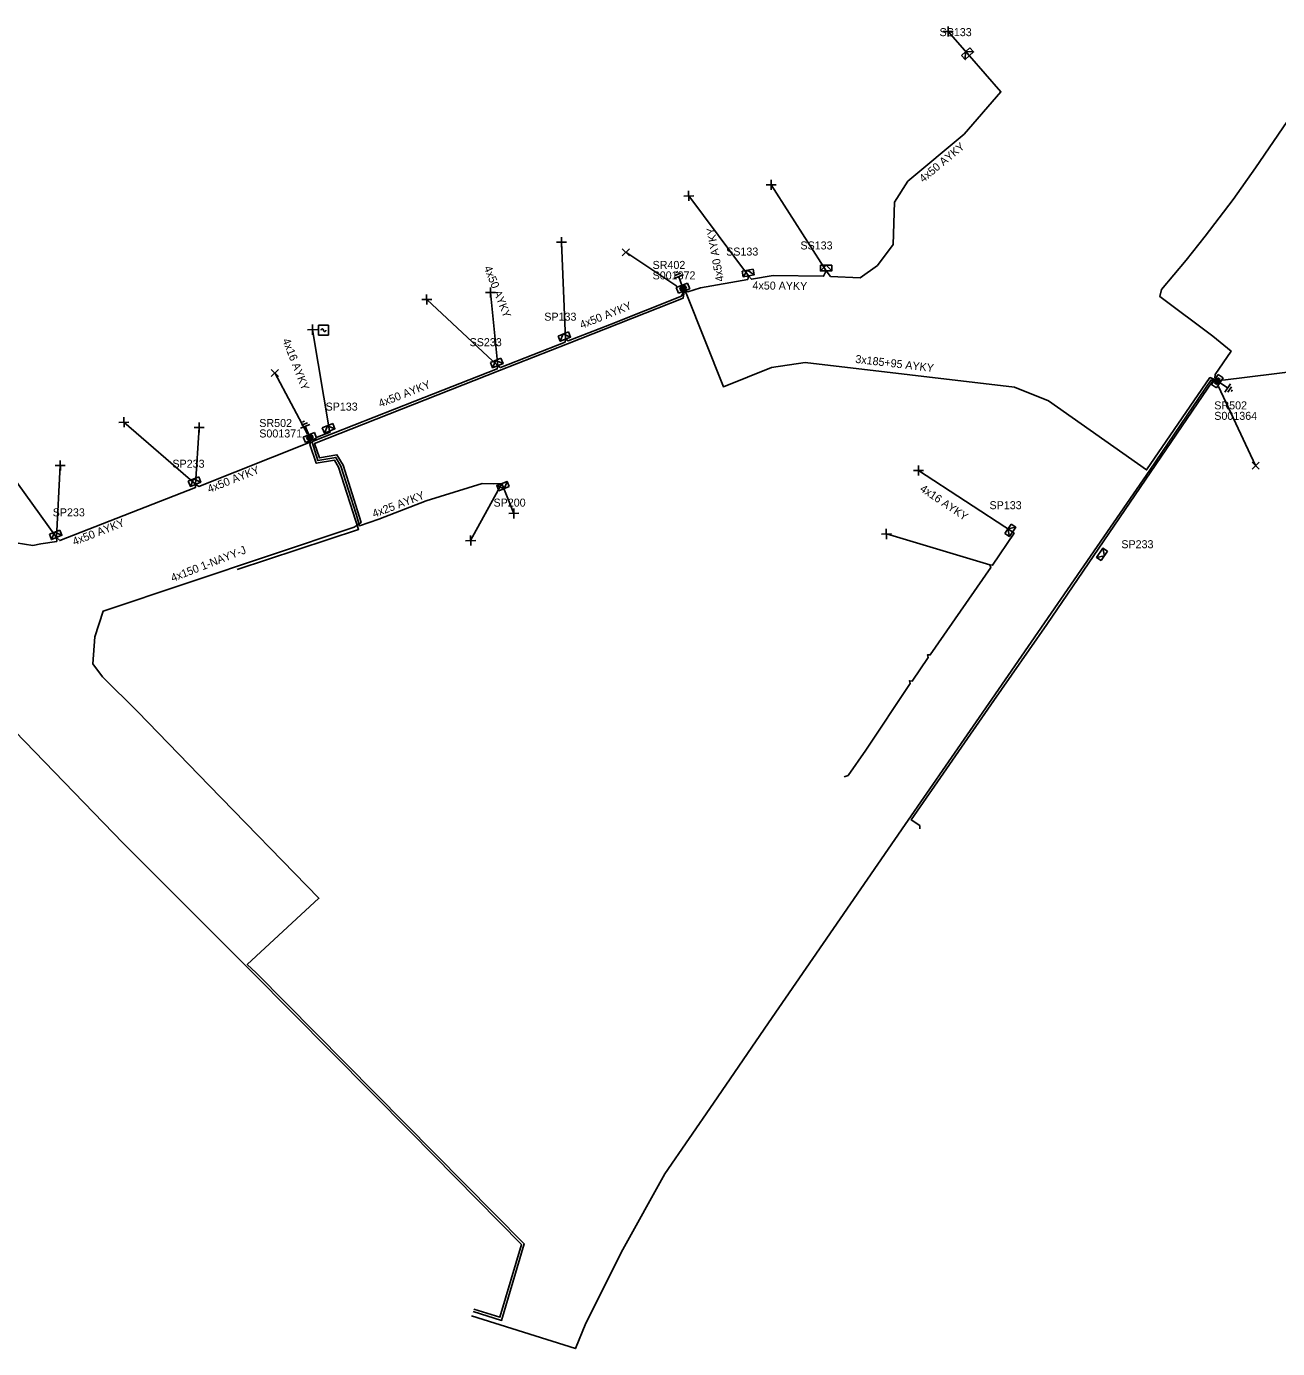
# Model space of a CAD drawing. Extents: x -762284 to -761419, y -1155250 to -1154991.
# Drawn here: x -761732.3 to -761576.8, y -1155250.1 to -1155085.8 of the extents above; entities that cross this region are included whole.
import ezdxf

# ---------------------------------------------------------------- set-up
doc = ezdxf.new("R2010")
doc.units = 0
for name, color, linetype in [('Vrstva 15', 7, 'Continuous'), ('Vrstva 28', 7, 'Continuous'), ('Vrstva 29', 7, 'Continuous'), ('Vrstva 30', 7, 'Continuous'), ('Vrstva 31', 7, 'Continuous'), ('Vrstva 33', 7, 'Continuous'), ('Vrstva 34', 7, 'Continuous'), ('Vrstva 5', 7, 'Continuous'), ('Vrstva 59', 7, 'Continuous'), ('Vrstva 6', 7, 'Continuous')]:
    doc.layers.add(name, color=color, linetype=linetype)

msp = doc.modelspace()

# ---------------------------------------------------------------- linework, layer by layer
at = {"layer": 'Vrstva 15'}
for points in [[(-761651.835, -1155117.141), (-761650.668, -1155116.693)], [(-761651.721, -1155116.765), (-761650.986, -1155116.483)], [(-761651.599, -1155116.382), (-761651.475, -1155116.334)], [(-761651.475, -1155116.334), (-761651.356, -1155116.288)], [(-761650.803, -1155118.084), (-761651.251, -1155116.917)], [(-761584.077, -1155130.034), (-761583.041, -1155130.733)], [(-761582.691, -1155130.215), (-761583.39, -1155131.252)], [(-761582.569, -1155130.589), (-761583.009, -1155131.241)], [(-761582.522, -1155131.083), (-761582.594, -1155131.189)], [(-761582.448, -1155130.973), (-761582.522, -1155131.083)], [(-761698.232, -1155135.733), (-761697.073, -1155135.265)], [(-761698.124, -1155135.355), (-761697.394, -1155135.06)], [(-761698.01, -1155134.969), (-761697.886, -1155134.92)], [(-761697.886, -1155134.92), (-761697.768, -1155134.872)], [(-761697.184, -1155136.658), (-761697.652, -1155135.499)]]:
    msp.add_lwpolyline(points, dxfattribs=at)
at = {"layer": 'Vrstva 28'}
for points in [[(-761650.156, -1155117.708), (-761651.547, -1155118.27)], [(-761651.547, -1155118.27), (-761651.266, -1155118.965)], [(-761650.43, -1155118.023), (-761651.12, -1155118.301)], [(-761651.12, -1155118.301), (-761650.979, -1155118.652)], [(-761650.457, -1155118.084), (-761651.059, -1155118.327)], [(-761651.059, -1155118.327), (-761650.953, -1155118.59)], [(-761650.483, -1155118.146), (-761650.997, -1155118.353)], [(-761650.997, -1155118.353), (-761650.927, -1155118.529)], [(-761650.953, -1155118.59), (-761650.35, -1155118.347)], [(-761650.509, -1155118.207), (-761650.936, -1155118.38)], [(-761650.927, -1155118.529), (-761650.412, -1155118.321)], [(-761650.9, -1155118.467), (-761650.473, -1155118.295)], [(-761650.529, -1155118.266), (-761650.88, -1155118.408)], [(-761650.473, -1155118.295), (-761650.509, -1155118.207)], [(-761650.412, -1155118.321), (-761650.483, -1155118.146)], [(-761650.35, -1155118.347), (-761650.457, -1155118.084)], [(-761650.289, -1155118.373), (-761650.43, -1155118.023)], [(-761649.875, -1155118.403), (-761650.156, -1155117.708)], [(-761651.266, -1155118.965), (-761649.875, -1155118.403)], [(-761650.979, -1155118.652), (-761650.289, -1155118.373)], [(-761650.936, -1155118.38), (-761650.9, -1155118.467)], [(-761584.192, -1155129.054), (-761585.031, -1155130.298)], [(-761584.255, -1155129.475), (-761584.671, -1155130.092)], [(-761584.242, -1155129.54), (-761584.605, -1155130.079)], [(-761584.229, -1155129.606), (-761584.54, -1155130.066)], [(-761584.216, -1155129.671), (-761584.474, -1155130.053)], [(-761584.412, -1155130.045), (-761584.2, -1155129.732)], [(-761584.409, -1155130.717), (-761583.57, -1155129.474)], [(-761584.396, -1155130.106), (-761584.138, -1155129.724)], [(-761584.383, -1155130.172), (-761584.073, -1155129.712)], [(-761584.37, -1155130.237), (-761584.007, -1155129.699)], [(-761584.357, -1155130.303), (-761583.941, -1155129.686)], [(-761583.941, -1155129.686), (-761584.255, -1155129.475)], [(-761584.007, -1155129.699), (-761584.242, -1155129.54)], [(-761584.073, -1155129.712), (-761584.229, -1155129.606)], [(-761584.138, -1155129.724), (-761584.216, -1155129.671)], [(-761583.57, -1155129.474), (-761584.192, -1155129.054)], [(-761585.031, -1155130.298), (-761584.409, -1155130.717)], [(-761584.671, -1155130.092), (-761584.357, -1155130.303)], [(-761584.605, -1155130.079), (-761584.37, -1155130.237)], [(-761584.54, -1155130.066), (-761584.383, -1155130.172)], [(-761584.474, -1155130.053), (-761584.396, -1155130.106)], [(-761696.526, -1155136.278), (-761697.917, -1155136.84)], [(-761696.245, -1155136.973), (-761696.526, -1155136.278)], [(-761697.917, -1155136.84), (-761697.636, -1155137.535)], [(-761697.636, -1155137.535), (-761696.245, -1155136.973)], [(-761696.8, -1155136.592), (-761697.49, -1155136.871)], [(-761697.49, -1155136.871), (-761697.348, -1155137.222)], [(-761696.826, -1155136.654), (-761697.429, -1155136.897)], [(-761697.429, -1155136.897), (-761697.322, -1155137.16)], [(-761696.852, -1155136.715), (-761697.367, -1155136.923)], [(-761697.367, -1155136.923), (-761697.296, -1155137.099)], [(-761697.348, -1155137.222), (-761696.658, -1155136.943)], [(-761697.322, -1155137.16), (-761696.72, -1155136.917)], [(-761696.878, -1155136.777), (-761697.306, -1155136.95)], [(-761697.306, -1155136.95), (-761697.27, -1155137.037)], [(-761697.296, -1155137.099), (-761696.781, -1155136.891)], [(-761697.27, -1155137.037), (-761696.843, -1155136.865)], [(-761696.899, -1155136.836), (-761697.249, -1155136.978)], [(-761696.843, -1155136.865), (-761696.878, -1155136.777)], [(-761696.781, -1155136.891), (-761696.852, -1155136.715)], [(-761696.72, -1155136.917), (-761696.826, -1155136.654)], [(-761696.658, -1155136.943), (-761696.8, -1155136.592)]]:
    msp.add_lwpolyline(points, dxfattribs=at)
at = {"layer": 'Vrstva 31'}
for points in [[(-761615.076, -1155088.479), (-761616.117, -1155089.416)], [(-761615.076, -1155088.479), (-761614.608, -1155088.999), (-761615.648, -1155089.936), (-761616.117, -1155089.416)], [(-761615.597, -1155088.947), (-761615.648, -1155089.936)], [(-761615.597, -1155088.947), (-761614.608, -1155088.999)], [(-761641.99, -1155115.988), (-761643.368, -1155116.231)], [(-761641.99, -1155115.988), (-761641.868, -1155116.677), (-761643.247, -1155116.92), (-761643.368, -1155116.231)], [(-761642.679, -1155116.109), (-761643.247, -1155116.92)], [(-761642.679, -1155116.109), (-761641.868, -1155116.677)], [(-761632.237, -1155115.49), (-761633.637, -1155115.49)], [(-761632.937, -1155115.49), (-761633.637, -1155116.19)], [(-761632.237, -1155115.49), (-761632.237, -1155116.19), (-761633.637, -1155116.19), (-761633.637, -1155115.49)], [(-761632.937, -1155115.49), (-761632.237, -1155116.19)], [(-761664.941, -1155123.767), (-761666.239, -1155124.292)], [(-761664.941, -1155123.767), (-761664.678, -1155124.416), (-761665.976, -1155124.941), (-761666.239, -1155124.292)], [(-761665.59, -1155124.029), (-761665.976, -1155124.941)], [(-761665.59, -1155124.029), (-761664.678, -1155124.416)], [(-761673.341, -1155127.057), (-761674.639, -1155127.582)], [(-761673.341, -1155127.057), (-761673.078, -1155127.706), (-761674.376, -1155128.231), (-761674.639, -1155127.582)], [(-761673.99, -1155127.319), (-761674.376, -1155128.231)], [(-761673.99, -1155127.319), (-761673.078, -1155127.706)], [(-761694.24, -1155135.167), (-761695.538, -1155135.692)], [(-761694.24, -1155135.167), (-761693.978, -1155135.816), (-761695.276, -1155136.341), (-761695.538, -1155135.692)], [(-761694.889, -1155135.429), (-761695.276, -1155136.341)], [(-761694.889, -1155135.429), (-761693.978, -1155135.816)], [(-761710.9, -1155141.787), (-761712.198, -1155142.312)], [(-761710.9, -1155141.787), (-761710.638, -1155142.436), (-761711.936, -1155142.961), (-761712.198, -1155142.312)], [(-761711.549, -1155142.049), (-761711.936, -1155142.961)], [(-761711.549, -1155142.049), (-761710.638, -1155142.436)], [(-761673.599, -1155143.523), (-761673.862, -1155142.874), (-761672.564, -1155142.349), (-761672.301, -1155142.998)], [(-761672.95, -1155143.261), (-761673.862, -1155142.874)], [(-761673.599, -1155143.523), (-761672.301, -1155142.998)], [(-761672.95, -1155143.261), (-761672.564, -1155142.349)], [(-761609.947, -1155147.656), (-761610.73, -1155148.816)], [(-761609.947, -1155147.656), (-761609.367, -1155148.047), (-761610.15, -1155149.208), (-761610.73, -1155148.816)], [(-761728.16, -1155148.398), (-761729.458, -1155148.922)], [(-761728.16, -1155148.398), (-761727.898, -1155149.047), (-761729.196, -1155149.571), (-761729.458, -1155148.922)], [(-761728.809, -1155148.66), (-761729.196, -1155149.571)], [(-761728.809, -1155148.66), (-761727.898, -1155149.047)], [(-761610.339, -1155148.236), (-761609.367, -1155148.047)], [(-761610.339, -1155148.236), (-761610.15, -1155149.208)], [(-761598.742, -1155152.175), (-761599.323, -1155151.783), (-761598.54, -1155150.622), (-761597.96, -1155151.014)], [(-761598.742, -1155152.175), (-761597.96, -1155151.014)], [(-761598.351, -1155151.594), (-761598.54, -1155150.622)], [(-761598.351, -1155151.594), (-761599.323, -1155151.783)]]:
    msp.add_lwpolyline(points, dxfattribs=at)
at = {"layer": 'Vrstva 34'}
for points in [[(-761618.385, -1155086.461), (-761617.135, -1155086.439)], [(-761617.749, -1155087.075), (-761617.771, -1155085.825)], [(-761639.739, -1155106.125), (-761639.761, -1155104.875)], [(-761649.989, -1155107.505), (-761650.011, -1155106.255)], [(-761640.375, -1155105.511), (-761639.125, -1155105.489)], [(-761650.625, -1155106.891), (-761649.375, -1155106.869)], [(-761666.435, -1155112.641), (-761665.185, -1155112.619)], [(-761665.799, -1155113.255), (-761665.821, -1155112.005)], [(-761658.252, -1155113.438), (-761657.368, -1155114.322)], [(-761658.252, -1155114.322), (-761657.368, -1155113.438)], [(-761674.619, -1155119.505), (-761674.641, -1155118.255)], [(-761683.185, -1155119.761), (-761681.935, -1155119.739)], [(-761682.549, -1155120.375), (-761682.571, -1155119.125)], [(-761675.255, -1155118.891), (-761674.005, -1155118.869)], [(-761696.739, -1155124.125), (-761696.761, -1155122.875)], [(-761694.766, -1155122.936), (-761696.016, -1155122.936)], [(-761696.016, -1155122.936), (-761696.016, -1155124.186)], [(-761694.766, -1155124.186), (-761694.766, -1155122.936)], [(-761697.375, -1155123.511), (-761696.125, -1155123.489)], [(-761696.016, -1155124.186), (-761694.766, -1155124.186)], [(-761695.391, -1155123.561), (-761695.391, -1155123.545), (-761695.394, -1155123.529), (-761695.398, -1155123.514), (-761695.404, -1155123.499), (-761695.411, -1155123.485), (-761695.419, -1155123.471), (-761695.429, -1155123.459), (-761695.441, -1155123.447), (-761695.453, -1155123.437), (-761695.466, -1155123.428), (-761695.48, -1155123.421), (-761695.495, -1155123.415), (-761695.511, -1155123.411), (-761695.527, -1155123.409), (-761695.543, -1155123.408), (-761695.558, -1155123.408), (-761695.574, -1155123.411), (-761695.59, -1155123.415), (-761695.605, -1155123.421), (-761695.619, -1155123.428), (-761695.632, -1155123.436), (-761695.645, -1155123.446), (-761695.656, -1155123.458), (-761695.666, -1155123.47), (-761695.675, -1155123.483), (-761695.682, -1155123.498), (-761695.688, -1155123.512), (-761695.692, -1155123.528), (-761695.695, -1155123.544), (-761695.696, -1155123.559), (-761695.696, -1155123.561)], [(-761695.391, -1155123.561), (-761695.39, -1155123.577), (-761695.388, -1155123.592), (-761695.384, -1155123.607), (-761695.379, -1155123.622), (-761695.372, -1155123.636), (-761695.364, -1155123.65), (-761695.354, -1155123.662), (-761695.343, -1155123.673), (-761695.331, -1155123.684), (-761695.318, -1155123.692), (-761695.304, -1155123.7), (-761695.29, -1155123.706), (-761695.275, -1155123.71), (-761695.259, -1155123.713), (-761695.244, -1155123.714), (-761695.228, -1155123.713), (-761695.212, -1155123.711), (-761695.197, -1155123.707), (-761695.182, -1155123.702), (-761695.168, -1155123.695), (-761695.155, -1155123.687), (-761695.142, -1155123.677), (-761695.131, -1155123.666), (-761695.121, -1155123.655), (-761695.112, -1155123.641), (-761695.105, -1155123.628), (-761695.099, -1155123.613), (-761695.094, -1155123.598), (-761695.092, -1155123.583), (-761695.09, -1155123.567), (-761695.09, -1155123.566)], [(-761701.882, -1155128.438), (-761700.998, -1155129.322)], [(-761701.882, -1155129.322), (-761700.998, -1155128.438)], [(-761720.179, -1155135.625), (-761720.201, -1155134.375)], [(-761720.815, -1155135.011), (-761719.565, -1155134.989)], [(-761711.465, -1155135.661), (-761710.215, -1155135.639)], [(-761710.829, -1155136.275), (-761710.851, -1155135.025)], [(-761728.725, -1155140.381), (-761727.475, -1155140.359)], [(-761728.089, -1155140.995), (-761728.111, -1155139.745)], [(-761622.065, -1155141.011), (-761620.815, -1155140.989)], [(-761621.429, -1155141.625), (-761621.451, -1155140.375)], [(-761580.002, -1155139.938), (-761579.118, -1155140.822)], [(-761580.002, -1155140.822), (-761579.118, -1155139.938)], [(-761671.719, -1155146.945), (-761671.741, -1155145.695)], [(-761672.355, -1155146.331), (-761671.105, -1155146.309)], [(-761677.089, -1155150.325), (-761677.111, -1155149.075)], [(-761626.065, -1155148.891), (-761624.815, -1155148.869)], [(-761625.429, -1155149.505), (-761625.451, -1155148.255)], [(-761677.725, -1155149.711), (-761676.475, -1155149.689)]]:
    msp.add_lwpolyline(points, dxfattribs=at)
at = {"layer": 'Vrstva 5'}
for points in [[(-761650.34, -1155118.73), (-761650.13, -1155118.81), (-761648.54, -1155118.32), (-761642.66, -1155117.26), (-761642.56, -1155116.8), (-761642.21, -1155117.23), (-761639.5, -1155116.77), (-761633.24, -1155116.85), (-761632.94, -1155116.19), (-761632.38, -1155116.89), (-761628.71, -1155117.07), (-761626.56, -1155115.54), (-761624.59, -1155112.93), (-761624.43, -1155107.65), (-761622.78, -1155105.05), (-761615.78, -1155099.22), (-761611.21, -1155093.95), (-761615.13, -1155089.47)], [(-761584.61, -1155129.5), (-761584.58, -1155129.06), (-761582.61, -1155126.15), (-761584.88, -1155124.31), (-761591.44, -1155119.38), (-761591.26, -1155118.52), (-761588.17, -1155114.87), (-761585.82, -1155111.9), (-761582.35, -1155107.33), (-761579.55, -1155103.39), (-761575.64, -1155097.65)], [(-761676.7, -1155245.18), (-761673.46, -1155246.2), (-761670.79, -1155237.14), (-761684.52, -1155223.2), (-761704.2, -1155203.38), (-761720.29, -1155187.3), (-761737.44, -1155169.6), (-761748.74, -1155161.1), (-761800.66, -1155115.37), (-761802.76, -1155113.49), (-761809.21, -1155107.71), (-761812.53, -1155106.85), (-761816.77, -1155107.49), (-761819.95, -1155109.3), (-761836.79, -1155127.18), (-761844.99, -1155135.76), (-761850.45, -1155130.54), (-761834.24, -1155112.53), (-761834.72, -1155111.94), (-761834.75, -1155111.9)], [(-761676.8, -1155245.47), (-761673.26, -1155246.58), (-761670.45, -1155237.06), (-761703.76, -1155203.39), (-761704.87, -1155202.38), (-761695.96, -1155194.14), (-761709.59, -1155180.14), (-761718.48, -1155170.96), (-761722.84, -1155166.64), (-761724.07, -1155165.03), (-761723.81, -1155161.65), (-761722.75, -1155158.45), (-761691.57, -1155148.05), (-761690.72, -1155147.47), (-761692.96, -1155140.34), (-761693.72, -1155139.03), (-761695.88, -1155139.42), (-761696.5, -1155137.62), (-761673.53, -1155128.59), (-761665.08, -1155125.24), (-761650.68, -1155119.57), (-761650.59, -1155119.04), (-761650.58, -1155118.82)], [(-761650.7, -1155118.87), (-761650.9, -1155119.33), (-761659.84, -1155122.91), (-761664.97, -1155124.88), (-761665.33, -1155124.67), (-761665.36, -1155125.03), (-761673.4, -1155128.21), (-761673.73, -1155127.97), (-761673.8, -1155128.37), (-761684.05, -1155132.4), (-761696.66, -1155137.36), (-761696.71, -1155137.3)], [(-761650.46, -1155118.77), (-761650.3, -1155118.96), (-761645.68, -1155130.58), (-761639.7, -1155128.2), (-761635.52, -1155127.56), (-761609.52, -1155130.64), (-761605.28, -1155132.32), (-761593.11, -1155140.92), (-761585.24, -1155129.44), (-761584.7, -1155129.64)], [(-761676.98, -1155246.03), (-761664.09, -1155250.08), (-761662.77, -1155246.92), (-761658.18, -1155237.76), (-761652.95, -1155228.39), (-761646.93, -1155219.59), (-761640.09, -1155209.63), (-761623.09, -1155184.97), (-761612.34, -1155169.4), (-761592.71, -1155140.96), (-761585.06, -1155129.71), (-761584.79, -1155129.75)], [(-761584.89, -1155129.87), (-761605.51, -1155160.11), (-761612.09, -1155169.57), (-761622.35, -1155184.4), (-761621.3, -1155185.11), (-761621.29, -1155185.51)], [(-761696.16, -1155136.84), (-761694.57, -1155136.22), (-761694.62, -1155136.08)], [(-761697.08, -1155137.44), (-761697.24, -1155137.56), (-761710.9, -1155142.98), (-761711.29, -1155142.7), (-761711.3, -1155143.11), (-761728.16, -1155149.69), (-761728.55, -1155149.31), (-761728.54, -1155149.81), (-761730.53, -1155150.11), (-761731.5, -1155150.3), (-761733.59, -1155150), (-761736.81, -1155148.91), (-761743.2, -1155145.87), (-761746.18, -1155143.14), (-761745.95, -1155142.83)], [(-761696.95, -1155137.4), (-761697.08, -1155137.78), (-761696.28, -1155140.1), (-761694.03, -1155139.69), (-761693.52, -1155140.58), (-761691.02, -1155148.31), (-761706.13, -1155153.28)], [(-761673.21, -1155142.61), (-761674.26, -1155142.64), (-761675.66, -1155142.6), (-761682.61, -1155144.78), (-761688.52, -1155147.02), (-761690.93, -1155147.86), (-761691.31, -1155146.43), (-761693.24, -1155140.46), (-761693.87, -1155139.36), (-761696.08, -1155139.76), (-761696.83, -1155137.35)], [(-761630.7, -1155179.06), (-761630.19, -1155178.88), (-761628.01, -1155175.72), (-761622.48, -1155167.45), (-761622.57, -1155167.12), (-761622.22, -1155167.15), (-761620.24, -1155164.24), (-761620.32, -1155163.89), (-761619.99, -1155163.9), (-761612.47, -1155153.06), (-761612.58, -1155152.72), (-761612.25, -1155152.76), (-761609.57, -1155148.78), (-761609.76, -1155148.63)]]:
    msp.add_lwpolyline(points, dxfattribs=at)
at = {"layer": 'Vrstva 59'}
for points in [[(-761615.13, -1155089.47), (-761617.76, -1155086.45)], [(-761632.94, -1155116.19), (-761639.75, -1155105.5)], [(-761642.56, -1155116.8), (-761650, -1155106.88)], [(-761665.33, -1155124.68), (-761665.81, -1155112.63)], [(-761651.47, -1155118.08), (-761657.81, -1155113.88)], [(-761673.73, -1155127.97), (-761682.56, -1155119.75)], [(-761673.73, -1155127.97), (-761674.63, -1155118.88)], [(-761694.63, -1155136.08), (-761696.75, -1155123.5)], [(-761697.36, -1155136.47), (-761701.44, -1155128.88)], [(-761583.63, -1155129.75), (-761573.91, -1155128.57)], [(-761584.15, -1155130.57), (-761579.56, -1155140.38)], [(-761728.55, -1155149.31), (-761740.25, -1155133.13)], [(-761711.29, -1155142.7), (-761720.19, -1155135)], [(-761711.29, -1155142.7), (-761710.84, -1155135.65)], [(-761728.55, -1155149.31), (-761728.1, -1155140.37)], [(-761609.76, -1155148.63), (-761621.44, -1155141)], [(-761673.21, -1155142.61), (-761677.1, -1155149.7)], [(-761673.21, -1155142.61), (-761671.73, -1155146.32)], [(-761612.58, -1155152.72), (-761625.44, -1155148.88)]]:
    msp.add_lwpolyline(points, dxfattribs=at)

# ---------------------------------------------------------------- texts
at = {"layer": 'Vrstva 29'}
for s, p in [('S001372', (-761654.49, -1155117.25)), ('S001364', (-761584.69, -1155134.7)), ('S001371', (-761703.37, -1155136.89))]:
    msp.add_text(s, height=0.9943, dxfattribs=at).set_placement(p)
at = {"layer": 'Vrstva 30'}
for s, p in [('SR402', (-761654.49, -1155115.95)), ('SR502', (-761584.69, -1155133.4)), ('SR502', (-761703.37, -1155135.59))]:
    msp.add_text(s, height=0.9943, dxfattribs=at).set_placement(p)
at = {"layer": 'Vrstva 33'}
for s, p in [('SS133', (-761618.83, -1155087.03)), ('SS133', (-761645.35, -1155114.29)), ('SS133', (-761636.12, -1155113.53)), ('SP133', (-761667.95, -1155122.38)), ('SS233', (-761677.23, -1155125.55)), ('SP133', (-761695.13, -1155133.55)), ('SP233', (-761714.16, -1155140.65)), ('SP200', (-761674.26, -1155145.48)), ('SP233', (-761729.04, -1155146.69)), ('SP133', (-761612.62, -1155145.8)), ('SP233', (-761596.24, -1155150.65))]:
    msp.add_text(s, height=0.9943, dxfattribs=at).set_placement(p)
at = {"layer": 'Vrstva 6'}
for s, height, rotation, p in [('4x50 AYKY', 0.9943, 39.76773, (-761620.85, -1155105.27)), ('4x50 AYKY', 0.9943, 100.14356, (-761645.63, -1155117.44)), ('4x50 AYKY', 0.9943, 291.59338, (-761675.47, -1155115.79)), ('4x50 AYKY', 0.9943, 359.3051, (-761642.08, -1155118.49)), ('4x50 AYKY', 0.9943, 21.83565, (-761663.31, -1155123.41)), ('4x16 AYKY', 0.9943, 291.38406, (-761700.52, -1155124.8)), ('3x185+95 AYKY', 0.99429, 353.22918, (-761629.33, -1155127.61)), ('4x50 AYKY', 0.9943, 21.47092, (-761688.33, -1155133.17)), ('4x50 AYKY', 0.9943, 21.64794, (-761709.58, -1155143.79)), ('4x16 AYKY', 0.9943, 326.09438, (-761621.36, -1155143.48)), ('4x25 AYKY', 0.9943, 20.75764, (-761689.1, -1155146.87)), ('4x50 AYKY', 0.9943, 21.32525, (-761726.35, -1155150.33)), ('4x150 1-NAYY-J', 0.99429, 21.37641, (-761714.13, -1155154.85))]:
    msp.add_text(s, height=height, rotation=rotation, dxfattribs=at).set_placement(p)

doc.saveas('drawing.dxf')
